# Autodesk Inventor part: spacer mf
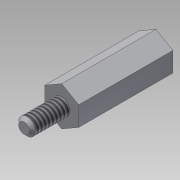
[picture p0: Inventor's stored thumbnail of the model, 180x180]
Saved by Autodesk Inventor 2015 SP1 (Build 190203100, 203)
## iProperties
Created: 2015-05
Part Number: spacer mf
Material: Acetal Resin, White
Document SubType Name: Modeling
Designer: kazys
Density: 1.425 g/cm^3
Appearance: Smooth - White
Description: 5/8" spacer
Author: kazys
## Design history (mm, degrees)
sketch "Sketch1"
  geometry: L1 (0, 3.3)-(2.857, 1.65); L2 (2.857, 1.65)-(2.857, -1.65); L3 (2.857, -1.65)-(0, -3.3); L4 (0, -3.3)-(-2.858, -1.65); L5 (-2.858, -1.65)-(-2.858, 1.65); L6 (-2.858, 1.65)-(0, 3.3); 2 further points
  constraints: 12 end point, 1 coincident, 13 other
  dimensions: "d0" = 5.715 distance between parallel lines of L2 L5
extrude "Extrusion1" new body sketch "Sketch1" distance "d1" = 15.875; taper "d2" = 0 deg
sketch "Sketch2"
  geometry: C1 r 1.422 at (0, 0); 1 further point
  constraints: 1 centre point, 1 coincident
  dimensions: "d3" = 2.8448 diameter of C1
extrude "Extrusion2" join sketch "Sketch2" distance "d4" = 6.35; taper "d5" = 0 deg
chamfer "Chamfer1" distance "d6" = 0.508; stored, may be unused: second distance "d7" = 3.175, angle "d8" = 45 deg
thread "Thread1" dims "d9" = 25.4, "d10" = 0
sketch "Sketch3"
  geometry: 2 further points
  constraints: 1 coincident
hole "Hole1" sketch "Sketch3" at (0, 0) diameter "d11" = 2.159; stored, may be unused: countersink angle "d15" = 82 deg, drill point angle "d17" = 118 deg; dims "d12" = 5.6896, "d13" = 9.525, "d14" = 6.35, "d16" = 8.8646
body "Solid1"
